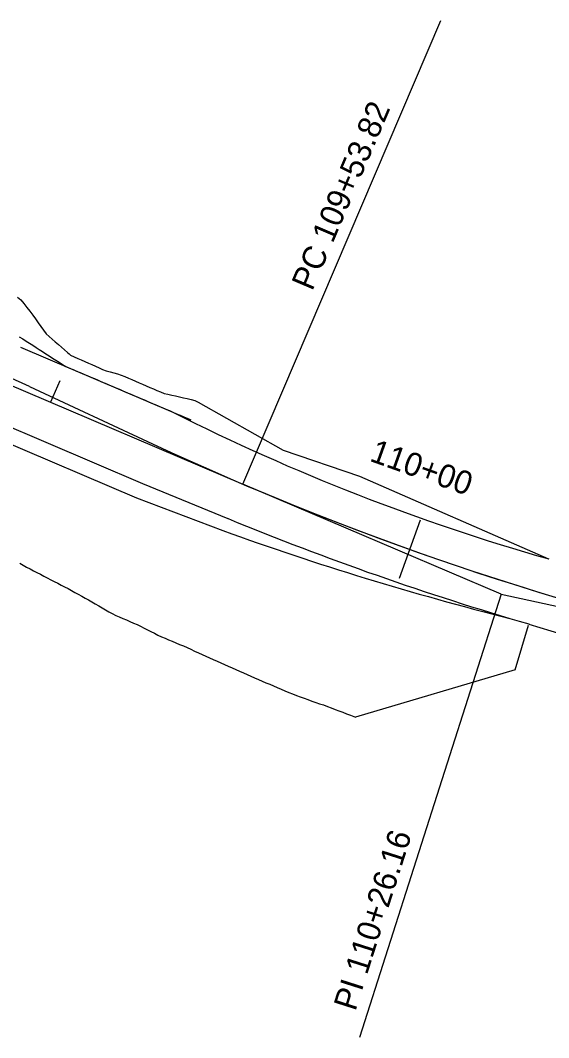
# Model space of a CAD drawing. Extents: x 834421 to 837111, y 495679 to 497078.
# Drawn here: x 835655.4 to 835791.5, y 496747.1 to 497009.4 of the extents above; entities that cross this region are included whole.
import ezdxf

# ---------------------------------------------------------------- set-up
doc = ezdxf.new("R2010")
doc.units = 0
for name, color, linetype in [('EXISTING CENTERLINE', 7, 'Continuous'), ('R_Horz Alg', 7, 'Continuous'), ('R_Horz Alg Annot', 7, 'Continuous'), ('R_Horz Alg Stationing', 7, 'Continuous'), ('R_Proposed Const Limits', 7, 'Continuous'), ('R_Proposed Road', 7, 'Continuous'), ('R_Shld', 7, 'Continuous'), ('R_Shoulder', 7, 'Continuous'), ('Transportation__x002e__STATEWIDE_HIGHWAY_LOGMILES_AHTD_point', 7, 'Continuous')]:
    doc.layers.add(name, color=color, linetype=linetype)

msp = doc.modelspace()

# ---------------------------------------------------------------- linework, layer by layer
at = {"layer": 'EXISTING CENTERLINE'}
msp.add_line((835657.74, 496914.96), (835689.37, 496900.19), dxfattribs=at)
for centre, radius, start, end in [((835558.82, 496703.05), 233.86, 64.9752, 111.7879), ((836012.53, 497592.42), 763.94, 244.97523, 257.70667)]:
    msp.add_arc(centre, radius, start, end, dxfattribs=at)
at = {"layer": 'R_Horz Alg'}
msp.add_line((835651.43, 496915.92), (835712.65, 496889.79), dxfattribs=at)
msp.add_line((835651.43, 496915.92), (835712.65, 496889.79), dxfattribs=at)
msp.add_arc((836012.53, 497592.42), 763.94, 246.8875, 257.70667, dxfattribs=at)
msp.add_arc((836012.53, 497592.42), 763.94, 246.8875, 257.70667, dxfattribs=at)
at = {"layer": 'R_Horz Alg Annot'}
for q in [(835712.65, 496889.79), (835879.68, 496839.5)]:
    msp.add_line((835779.19, 496861.39), q, dxfattribs=at)
for points in [[(835712.65, 496889.79), (835763.68, 497009.36)], [(835779.19, 496861.39), (835742.7, 496747.08)]]:
    msp.add_lwpolyline(points, dxfattribs=at)
at = {"layer": 'R_Horz Alg Stationing'}
for points in [[(835665.51, 496916.44), (835663.15, 496910.92)], [(835758.34, 496880.49), (835752.96, 496865.42)]]:
    msp.add_lwpolyline(points, dxfattribs=at)
at = {"layer": 'R_Proposed Const Limits'}
for q in [(835786.25, 496853.4), (835741.66, 496829.73)]:
    msp.add_line((835782.83, 496841.89), q, dxfattribs=at)
for points in [[(835654.6, 496937.97), (835655.5, 496937.29), (835656.29, 496936.32), (835657.05, 496935.33), (835657.81, 496934.34), (835658.57, 496933.34), (835659.26, 496932.37), (835659.94, 496931.41), (835660.62, 496930.45), (835661.3, 496929.5), (835661.98, 496928.55), (835662.76, 496927.83), (835663.55, 496927.14), (835664.35, 496926.45), (835665.14, 496925.76), (835665.93, 496925.08), (835666.73, 496924.39), (835667.52, 496923.7), (835668.31, 496923), (835669.23, 496922.6), (835670.14, 496922.2), (835671.06, 496921.8), (835671.97, 496921.39), (835672.89, 496920.99), (835673.8, 496920.59), (835674.72, 496920.19), (835675.63, 496919.79), (835676.55, 496919.38), (835677.47, 496919), (835678.45, 496918.74), (835679.43, 496918.49), (835680.41, 496918.23), (835681.36, 496917.91), (835682.28, 496917.51), (835683.19, 496917.12), (835684.11, 496916.72), (835685.03, 496916.32), (835685.95, 496915.92), (835686.86, 496915.53), (835687.78, 496915.13), (835688.7, 496914.73), (835689.62, 496914.34), (835690.54, 496913.94), (835691.45, 496913.54), (835692.38, 496913.16), (835693.37, 496912.94), (835694.37, 496912.73), (835695.36, 496912.51), (835696.36, 496912.29), (835697.35, 496912.07), (835698.35, 496911.86), (835699.34, 496911.63), (835700.3, 496911.33), (835701.2, 496910.89)], [(835654.6, 496937.97), (835655.5, 496937.29), (835656.29, 496936.32), (835657.05, 496935.33), (835657.81, 496934.34), (835658.57, 496933.34), (835659.26, 496932.37), (835659.94, 496931.41), (835660.62, 496930.45), (835661.3, 496929.5), (835661.98, 496928.55), (835662.76, 496927.83), (835663.55, 496927.14), (835664.35, 496926.45), (835665.14, 496925.76), (835665.93, 496925.08), (835666.73, 496924.39), (835667.52, 496923.7), (835667.9, 496923.37)], [(835701.2, 496910.89), (835723.05, 496898.5), (835742.69, 496891.88), (835791.45, 496870.49)], [(835655.21, 496869.39), (835656.09, 496868.89), (835656.96, 496868.4), (835657.85, 496867.93), (835658.74, 496867.46), (835659.63, 496867), (835660.52, 496866.54), (835661.41, 496866.08), (835662.3, 496865.61), (835663.19, 496865.15), (835664.08, 496864.69), (835664.97, 496864.23), (835665.86, 496863.77), (835666.75, 496863.3), (835667.64, 496862.84), (835668.52, 496862.37), (835669.4, 496861.88), (835670.28, 496861.39), (835671.16, 496860.9), (835672.04, 496860.41), (835672.92, 496859.92), (835673.79, 496859.43), (835674.66, 496858.92), (835675.53, 496858.4), (835676.4, 496857.89), (835677.27, 496857.38), (835678.14, 496856.87)], [(835678.14, 496856.87), (835679.03, 496856.4), (835679.92, 496855.95), (835680.84, 496855.55), (835681.76, 496855.16), (835682.68, 496854.76), (835683.59, 496854.37), (835684.51, 496853.97), (835685.43, 496853.58), (835686.33, 496853.15), (835687.23, 496852.69), (835688.12, 496852.23), (835689.01, 496851.78), (835689.91, 496851.32), (835690.8, 496850.87), (835691.71, 496850.45), (835692.63, 496850.06), (835693.55, 496849.67), (835694.47, 496849.28), (835695.4, 496848.89), (835696.38, 496848.48), (835697.35, 496848.07), (835698.33, 496847.65), (835699.29, 496847.21), (835700.25, 496846.76), (835701.21, 496846.31), (835702.17, 496845.87), (835703.13, 496845.43), (835704.09, 496844.99), (835705.06, 496844.55), (835706.02, 496844.11), (835706.99, 496843.67), (835707.96, 496843.24), (835708.92, 496842.82), (835709.89, 496842.39), (835710.86, 496841.97), (835711.84, 496841.54), (835712.81, 496841.12), (835713.78, 496840.7), (835714.75, 496840.27), (835715.72, 496839.85), (835716.69, 496839.42), (835717.66, 496839), (835718.64, 496838.59), (835719.61, 496838.17), (835720.59, 496837.75), (835721.56, 496837.34), (835722.54, 496836.92), (835723.51, 496836.51), (835724.49, 496836.1), (835725.48, 496835.71), (835726.47, 496835.33), (835727.46, 496834.96), (835728.45, 496834.59), (835729.44, 496834.22), (835730.43, 496833.85), (835731.44, 496833.51), (835732.45, 496833.18), (835733.45, 496832.85), (835734.45, 496832.48), (835735.44, 496832.1), (835736.42, 496831.72), (835737.41, 496831.34), (835738.4, 496830.96), (835739.39, 496830.59), (835740.38, 496830.21), (835741.66, 496829.73)]]:
    msp.add_lwpolyline(points, dxfattribs=at)
at = {"layer": 'R_Proposed Road'}
for p, q in [((835655.35, 496925.12), (835694.67, 496908.34)), ((835647.5, 496906.72), (835686.82, 496889.94)), ((835686.82, 496889.94), (835708.85, 496880.89)), ((835786.35, 496853.73), (835786.34, 496853.69))]:
    msp.add_line(p, q, dxfattribs=at)
msp.add_lwpolyline([(835786.34, 496853.69), (835800.56, 496849.36), (835824.59, 496842.64), (835839.54, 496839.06), (835854.5, 496835.48), (835870.61, 496832.58), (835886.72, 496829.69), (835903.42, 496827.39), (835920.11, 496825.1), (835934.87, 496823.71)], dxfattribs=at)
for centre, radius, start, end in [((835940.09, 497393.88), 544.04, 243.1853, 254.149), ((836002.87, 497595.84), 773.05, 247.64564, 253.73499)]:
    msp.add_arc(centre, radius, start, end, dxfattribs=at)
at = {"layer": 'R_Shld'}
msp.add_lwpolyline([(835655.06, 496927.78), (835655.96, 496927.22), (835656.83, 496926.67), (835657.68, 496926.12), (835658.53, 496925.57), (835659.39, 496925.03), (835660.24, 496924.48), (835661.1, 496923.94), (835661.95, 496923.39), (835662.81, 496922.84), (835663.66, 496922.3), (835664.51, 496921.75), (835665.37, 496921.21), (835666.22, 496920.66), (835667.08, 496920.12), (835668, 496919.72), (835668.92, 496919.33), (835669.84, 496918.94), (835670.76, 496918.55), (835671.68, 496918.15), (835672.6, 496917.76), (835673.52, 496917.37), (835674.44, 496916.98), (835675.36, 496916.58), (835676.27, 496916.19), (835677.19, 496915.8), (835678.11, 496915.4), (835679.03, 496915.01), (835679.95, 496914.62), (835680.87, 496914.23), (835681.79, 496913.83), (835682.71, 496913.44), (835683.63, 496913.05), (835684.55, 496912.66), (835685.47, 496912.26), (835686.39, 496911.87), (835687.31, 496911.48), (835688.23, 496911.09), (835689.15, 496910.69), (835690.07, 496910.3), (835690.99, 496909.91), (835691.91, 496909.52), (835692.83, 496909.12), (835693.75, 496908.73), (835694.67, 496908.34), (835695.59, 496907.95), (835696.51, 496907.55), (835697.43, 496907.16), (835698.35, 496906.77), (835699.27, 496906.38)], dxfattribs=at)
at = {"layer": 'R_Shoulder'}
for p, q in [((835645.93, 496903.05), (835685.25, 496886.27)), ((835685.25, 496886.27), (835707.53, 496877.79))]:
    msp.add_line(p, q, dxfattribs=at)
msp.add_arc((835970.5, 497605.29), 773.57, 250.12645, 255.85829, dxfattribs=at)
at = {"layer": 'Transportation__x002e__STATEWIDE_HIGHWAY_LOGMILES_AHTD_point'}
msp.add_line((835700.04, 496894.98), (835700.04, 496894.98), dxfattribs=at)

# ---------------------------------------------------------------- texts
at = {"layer": 'R_Horz Alg Annot'}
for s, rotation, p in [('PC 109+53.82', 66.8875, (835730.55, 496939.37)), ('PI 110+26.16', 72.2971, (835741.66, 496753.71))]:
    msp.add_text(s, height=6, rotation=rotation, dxfattribs=at).set_placement(p)
at = {"layer": 'R_Horz Alg Stationing'}
msp.add_text('110+00', height=6, rotation=340.3511, dxfattribs=at).set_placement((835745.08, 496895.84))

doc.saveas('drawing.dxf')
